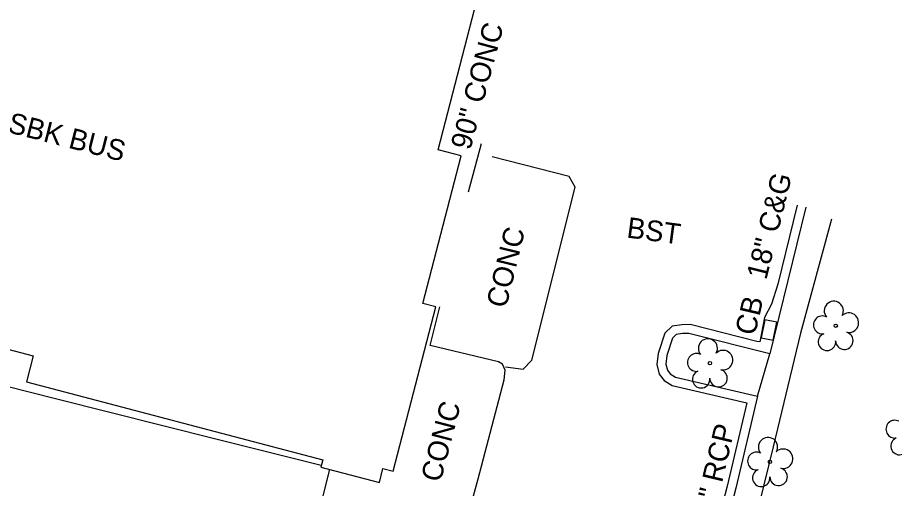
# Model space of a CAD drawing. Extents: x 2089016 to 2094354, y 862840 to 864725.
# Drawn here: x 2092662.4 to 2092832.5, y 863781.3 to 863872.6 of the extents above; entities that cross this region are included whole.
import ezdxf

# ---------------------------------------------------------------- set-up
doc = ezdxf.new("R2010")
doc.units = 0
for name, color, linetype in [('Exist Building', 7, 'Continuous'), ('Exist Building Text', 7, 'Continuous'), ('Exist Roads Change in Surface', 7, 'Continuous'), ('Exist Roads Curbs', 7, 'Continuous'), ('Exist Roads Curbs Text', 7, 'Continuous'), ('Exist Roads EOP', 7, 'Continuous'), ('Exist Roads EOP Other', 7, 'Continuous'), ('Exist Roads EOP Other Text', 7, 'Continuous'), ('Exist Structure Minor Catch Basin', 7, 'Continuous'), ('Exist Structure Minor Catch Basin Text', 7, 'Continuous'), ('Exist Structure Minor Pipes RCP 15 Inch Text', 7, 'Continuous'), ('Exist Vegetation Hedge Row', 7, 'Continuous'), ('Exist Vegetation Tree CELL', 7, 'Continuous')]:
    doc.layers.add(name, color=color, linetype=linetype)

msp = doc.modelspace()

# ---------------------------------------------------------------- linework, layer by layer
at = {"layer": 'Exist Building'}
msp.add_lwpolyline([(2092756.25, 863894.19), (2092665.24, 863917.88), (2092666.15, 863921.34), (2092645.24, 863926.78), (2092644.29, 863923.13), (2092623.49, 863928.56), (2092621.58, 863921.25), (2092614.58, 863923.08), (2092609.29, 863902.85), (2092615.61, 863901.2), (2092595.79, 863825.31), (2092665.45, 863807.01), (2092664.13, 863801.99), (2092721.6, 863786.89), (2092721.21, 863785.43), (2092732.59, 863782.48), (2092733.29, 863785.17), (2092735.29, 863784.65), (2092743.57, 863816.52), (2092741.04, 863817.18), (2092748.49, 863845.81), (2092743.99, 863846.98)], close=True, dxfattribs=at)
at = {"layer": 'Exist Roads Change in Surface'}
msp.add_lwpolyline([(2092757.08, 863804.87), (2092760.49, 863804.47), (2092762.15, 863806.2), (2092770.56, 863839.7), (2092769.44, 863841.8), (2092754.47, 863845.58)], dxfattribs=at)
at = {"layer": 'Exist Roads Curbs'}
for points in [[(2092749.89, 863838.84), (2092752.4, 863848.16)], [(2092815.32, 863835.85), (2092808.32, 863807.4), (2092792.65, 863811.35), (2092791.42, 863811.35), (2092790.2, 863811.14), (2092789.48, 863810.47), (2092788.37, 863807.08), (2092788.14, 863805.44), (2092788.46, 863804.25), (2092789.01, 863803.53), (2092790.06, 863802.86), (2092805.95, 863799.2), (2092801.73, 863781.37), (2092796.95, 863762.92), (2092792.24, 863743.71), (2092790.76, 863737.65)], [(2092595.04, 863817.06), (2092593.84, 863811.55), (2092593.37, 863809.52), (2092593.39, 863808.39), (2092593.86, 863807.06), (2092594.74, 863805.93), (2092596.22, 863805.19), (2092613.77, 863798.93), (2092618.52, 863797.27), (2092619.71, 863797.26), (2092621.5, 863797.67), (2092622.91, 863798.78), (2092623.42, 863799.4), (2092625.91, 863810.13), (2092650.06, 863803.75), (2092669.77, 863798.76), (2092701.13, 863790.9), (2092721.31, 863785.81)], [(2092744.69, 863775.86), (2092749.6, 863778.62), (2092750.83, 863779.91), (2092751.77, 863783.19), (2092756.78, 863802.38), (2092756.98, 863804.25), (2092756.46, 863805.43), (2092755.72, 863805.88), (2092742.47, 863809.01), (2092744.3, 863816.53)], [(2092722.89, 863785), (2092719.96, 863773.22), (2092719.89, 863771.71), (2092720.31, 863770.82), (2092722.3, 863770.11), (2092730.7, 863768.03), (2092732.12, 863768.41), (2092734.92, 863770.04), (2092738.43, 863772.18)]]:
    msp.add_lwpolyline(points, dxfattribs=at)
at = {"layer": 'Exist Roads EOP'}
msp.add_spline([(2092351.39, 863867.42), (2092346.28, 863853.71), (2092340.44, 863838.83), (2092338.02, 863832.45), (2092326.59, 863809.54), (2092324.18, 863804.42), (2092322.34, 863798.11), (2092322.21, 863794.63), (2092323.26, 863788.18), (2092325.31, 863783.21), (2092329.49, 863777.7), (2092333.36, 863774.11), (2092338.14, 863771.94), (2092365.19, 863764.36), (2092404.76, 863753.49), (2092444.45, 863742.49), (2092470.82, 863735.23), (2092515.55, 863722.74), (2092529.36, 863718.89), (2092533.92, 863717.65), (2092575.11, 863706.35), (2092620.49, 863693.63), (2092661.52, 863682.27), (2092704.83, 863670.36)], degree=3, dxfattribs=at)
at = {"layer": 'Exist Roads EOP Other'}
for points in [[(2092813.65, 863836.26), (2092809.88, 863820.94)], [(2092809.88, 863820.94), (2092808.66, 863817.07), (2092807.31, 863814.43)], [(2092807.31, 863814.43), (2092806.42, 863809.77), (2092805.79, 863809.81)], [(2092805.79, 863809.81), (2092792.86, 863813.07), (2092791.27, 863813.06), (2092789.41, 863812.75), (2092787.99, 863811.42), (2092786.7, 863807.47), (2092786.39, 863805.34), (2092786.89, 863803.48), (2092787.83, 863802.25), (2092789.39, 863801.25), (2092803.88, 863797.91), (2092800.06, 863781.78), (2092797.55, 863772.07)]]:
    msp.add_lwpolyline(points, dxfattribs=at)
msp.add_spline([(2092744.83, 863669.14), (2092739.53, 863670.51), (2092698.61, 863681.9), (2092655.56, 863693.83), (2092614.88, 863705.04), (2092572.51, 863716.82), (2092534.25, 863727.26), (2092490.85, 863739.3), (2092453.11, 863749.73), (2092413.17, 863760.74), (2092373.71, 863771.76), (2092342.37, 863780.54), (2092336.27, 863784.25), (2092333.6, 863789.3), (2092333.19, 863795.1), (2092333.89, 863798.65), (2092336.05, 863803.25), (2092354.66, 863838.72)], degree=3, dxfattribs=at)
at = {"layer": 'Exist Structure Minor Catch Basin'}
msp.add_lwpolyline([(2092807.37, 863814.01), (2092806.65, 863810.53), (2092808.98, 863810.05), (2092809.7, 863813.54)], close=True, dxfattribs=at)
at = {"layer": 'Exist Vegetation Hedge Row'}
msp.add_line((2092805.95, 863799.2), (2092808.32, 863807.4), dxfattribs=at)
msp.add_lwpolyline([(2092820.32, 863833.51), (2092814.3, 863811.45), (2092808.97, 863789.39), (2092802.74, 863763.85), (2092799.15, 863752.83), (2092798.63, 863745.55), (2092799.95, 863740.99)], dxfattribs=at)
at = {"layer": 'Exist Vegetation Tree CELL'}
for p, q in [((2092821.13, 863812.86), (2092821.13, 863812.86)), ((2092796.72, 863805.6), (2092796.72, 863805.6)), ((2092808.37, 863786.48), (2092808.37, 863786.48))]:
    msp.add_line(p, q, dxfattribs=at)
for centre in [(2092821.13, 863812.86), (2092796.72, 863805.6), (2092808.37, 863786.48)]:
    msp.add_circle(centre, 0.326, dxfattribs=at)
for centre, radius, start, end in [((2092820.75, 863815.74), 1.86, 330.1651, 219.7134), ((2092823.68, 863813.45), 1.9, 257.1011, 134.1999), ((2092818.52, 863813.02), 1.73, 62.6636, 279.3457), ((2092822.8, 863809.96), 1.7, 181.2822, 74.56), ((2092796.33, 863808.47), 1.86, 330.1651, 219.7134), ((2092819.43, 863809.74), 1.69, 111.5671, 6.231), ((2092794.11, 863805.75), 1.73, 62.6636, 279.3457), ((2092799.26, 863806.19), 1.9, 257.1011, 134.1999), ((2092795.01, 863802.48), 1.69, 111.5671, 6.231), ((2092798.39, 863802.7), 1.7, 181.2822, 74.56), ((2092832.6, 863792.81), 1.73, 62.6636, 279.3457), ((2092807.99, 863789.35), 1.86, 330.1651, 219.7134), ((2092833.5, 863789.53), 1.69, 111.5671, 6.231), ((2092805.76, 863786.63), 1.73, 62.6636, 279.3457), ((2092810.92, 863787.07), 1.9, 257.1011, 134.1999), ((2092806.67, 863783.36), 1.69, 111.5671, 6.231), ((2092810.04, 863783.58), 1.7, 181.2822, 74.56)]:
    msp.add_arc(centre, radius, start, end, dxfattribs=at)

# ---------------------------------------------------------------- texts
at = {"layer": 'Exist Building Text'}
msp.add_text('1SBK BUS', height=4, rotation=345.6281, dxfattribs=at).set_placement((2092657.39, 863851.15))
at = {"layer": 'Exist Roads Curbs Text'}
for s, rotation, p in [('90" CONC', 74.8988, (2092750.22, 863846.75)), ('18" C&G', 76.1753, (2092807.66, 863821.61)), ('CONC', 76.3488, (2092757.18, 863816.11)), ('CONC', 75.38, (2092744.45, 863782.35))]:
    msp.add_text(s, height=4, rotation=rotation, dxfattribs=at).set_placement(p)
at = {"layer": 'Exist Roads EOP Other Text'}
msp.add_text('BST', height=4, rotation=352.4157, dxfattribs=at).set_placement((2092780.43, 863829.97))
at = {"layer": 'Exist Structure Minor Catch Basin Text'}
msp.add_text('CB', height=4, rotation=76.7219, dxfattribs=at).set_placement((2092805.43, 863810.8))
at = {"layer": 'Exist Structure Minor Pipes RCP 15 Inch Text'}
msp.add_text('15" RCP', height=4, rotation=76.7345, dxfattribs=at).set_placement((2092796.92, 863773.2))

doc.saveas('drawing.dxf')
